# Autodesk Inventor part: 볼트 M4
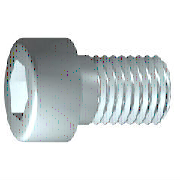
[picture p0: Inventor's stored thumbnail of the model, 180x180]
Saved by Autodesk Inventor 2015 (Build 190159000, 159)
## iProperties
IsCustomPart: 0
Created: 2012-02
Part Number: 볼트 M4
Material: 스테인리스강
Description: 6각 소켓 머리 캡 나사
Document SubType Name: Modeling
Standard: ISO 4762
Designer: mduedu
Standard Revision: Fourth edition 2004-03-01
Standards Organization: ISO
Language: ko-KR
Size Designation: M4 x 12
Categories: <MemberInstance><Categories><Category DisplayName="조임쇠" InternalName="e4da775c-781d-43d5-af7c-5136215cf5a6" Mnemonic="FSTN"><Category DisplayName="볼트" InternalN
Density: 8.08 g/cm^3
Mass: 2.29719 g
Surface Area: 3.30853 cm^2
Volume: 0.284306 cm^3
Appearance: 반광택
Author: mduedu
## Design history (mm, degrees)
sketch "스케치1"
  geometry: L1 (-1, 0)-(12, 0); L2 (12, 0)-(12, 2); L3 (12, 2)-(1.75, 2); L4 (1.75, 2)-(1.32, 2); L5 (1.32, 2)-(0, 2); L6 (0, 2)-(0, 3.5); L7 (0, 3.5)-(-4, 3.5); L8 (-4, 3.5)-(-4, 1.732); L9 (-4, 1.732)-(-2, 1.732); L10 (-2, 1.732)-(-1, 0); L11 (-7.2, 0)-(15.2, 0) reference; L12 (0, -0.7)-(0, 4.2) reference; L13 (1.75, 2)-(0, 2)
  constraints: 22 end point, 6 parallel, 2 collinear, 2 perpendicular, 1 horizontal, 1 point on line
  dimensions: "d1" = 10.25 distance from line of L3.end L2 (= GEL); "d2" = 0.42952 distance of L4.end L3.end (computed from GAL); "d3" = 4 distance between parallel lines of L8 L6 (= KOH); "d4" = 2 distance of L8.end L9.end (= INTI); "d5" = 60 deg angle of L10 L1; "d6" = 4 diameter of L3 L1 (= GD); "d7" = 4 diameter of L5 L1 (= BDM); "d8" = 3.4641 diameter of L9 L1 (= 1.1547 x SW); "d9" = 7 diameter of L7 L1 (= KOD); "d26" = 12 distance between parallel lines of L12 L2 (= NLG)
revolve "본체" sketch "스케치1" stored, may be unused: angle "d10" = 90 deg
sketch "스케치2"
  geometry: L1 (0, -4.9)-(0, 4.9) reference; L2 (-4.9, 0)-(4.9, 0) reference; L3 (1.732, 0)-(0.866, -1.5); L4 (0.866, -1.5)-(-0.866, -1.5); L5 (-0.866, -1.5)-(-1.732, 0); L6 (-1.732, 0)-(-0.866, 1.5); L7 (-0.866, 1.5)-(0.866, 1.5); L8 (0.866, 1.5)-(1.732, 0); 2 further points
  constraints: 12 end point, 1 coincident, 1 horizontal alignment, 1 point on line, 12 other
extrude "슬롯" join sketch "스케치2" stored distance "d11" = 10; taper "d12" = 0 deg
workplane "Work Plane1"
fillet "Fillet2" dims "d30" = 0.1 (= R)
body "Solid1"
fillet "모깎기1" dims "d17" = 0.4 (= RR)
feature "스레드" dims "d13" = 10.25 (= GEL), "d14" = 0
chamfer "모따기1" distance "d15" = 0.42941 (= -0.5 x SPD + 0.5 x GD); stored, may be unused: second distance "d16" = 0.42941 (= GUL), angle "d27" = 45 deg
other parameters: "GD" = 4 [user parameter; used in 2 equation terms], "NLG" = 12 [user parameter; used in 1 equation term], "GEL" = 10.25 [user parameter; used in 2 equation terms], "KOD" = 7 [user parameter; used in 1 equation term], "KOH" = 4 [user parameter; used in 1 equation term], "INTI" = 2 [user parameter; used in 1 equation term], "GAL" = 0.42941 (= 0.61345 x PTC) [user parameter; used in 1 equation term], "GUL" = 0.42941 (= 0.61345 x PTC) [user parameter; used in 1 equation term], "BDM" = 4 (= NND) [user parameter; used in 1 equation term], "SW" = 3 [user parameter; used in 2 equation terms], "RR" = 0.4 [user parameter; used in 1 equation term], "SPD" = 3.14117 (= NND - 1.2269 x PTC) [user parameter; used in 1 equation term], "d19" = 0, "d28" = 0, "d29" = 0, "R" = 0.1 [user parameter; used in 1 equation term], "TOA" = 30 deg [user parameter], "GD1" = 3.14117 (= THREADDIA - 1.2269 x PTC) [user parameter], "THREADDIA" = 4 [user parameter; used in 1 equation term], "FAWI" = 45 deg [user parameter], "TPU" = 14.28571 (computed from PTC) [user parameter], "PTC" = 0.7 [user parameter; used in 5 equation terms], "NND" = 4 [user parameter; used in 2 equation terms], "E0" = 3.465 (= 1.155 x SW) [user parameter]
